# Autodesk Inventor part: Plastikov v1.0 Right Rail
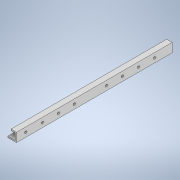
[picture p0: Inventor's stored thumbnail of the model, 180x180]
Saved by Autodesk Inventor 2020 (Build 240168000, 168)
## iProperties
Created: 2019-12
Part Number: Plastikov v1.0 Right Rail
Material: Generic
Document SubType Name: Modeling
Designer: Iv. Tr.
Density: 1 g/cm^3
Appearance: Default
Sending System: Autodesk Inventor 2020
Preprocessor: ST-DEVELOPER v18
Title: D:\~~GatCad\AK Rails\Plastikov v0.9 Right Rail.stp
Author: johne
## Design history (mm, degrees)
feature "Solid1"
sketch "Sketch1"
  geometry: L1 (0, 0)-(8.152, 0) reference; L2 (0, 0)-(0, 63.5); L3 (0, 172.769)-(0, 0) reference; L4 (0, 63.5)-(3.048, 63.5); L5 (3.048, 63.5)-(3.048, 82.55); L6 (3.048, 82.55)-(0, 82.55); L7 (0, 82.55)-(0, 63.5); 1 further point
  constraints: 10 end point, 2 parallel, 1 horizontal, 1 perpendicular, 1 point on line
  dimensions: "d0" = 63.5 distance of L1.start L2.end; "d1" = 3.048 distance of L6.end L5.end; "d2" = 19.05 distance of L5.end L4.end
extrude "Extrusion1" cut sketch "Sketch1" distance "d3" = 25.4; taper "d4" = 0 deg
body "Solid2"
